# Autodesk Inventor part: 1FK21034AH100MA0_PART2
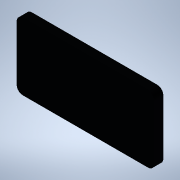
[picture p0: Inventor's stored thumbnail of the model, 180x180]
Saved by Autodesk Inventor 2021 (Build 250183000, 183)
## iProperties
Created: 2025-04
Part Number: 1FK21034AH100MA0_PART2
Material: Generic
Catalog Web Link: www.3dfindit.com
Description: -Servo synchronous motor
Document SubType Name: Modeling
Designer: psAdmin
Mass: 2.9597 g
Surface Area: 23.6483 cm^2
Volume: 2.9597 cm^3
Density: 1 g/cm^3
Appearance: PSOLRGB-38-46-56
Category: PARTsolutions
Title: 1FK21034AH100MA0_PART2
Author: Cadenas PARTsolutions
Comments: Servo synchronous motor
Sending System: PARTsolutions
Preprocessor: ST-DEVELOPER v19.3
PSOL_IDENT_0: {$CADENAS_DATA/23d-libs/siemens_ag/_cat_/39/97/1fk21034ah100ma0.prj},213 {VTYP=3D},{NB=1FK21034AH100
PSOL_IDENT_1: MA0_PART2},{LINA=1FK21034AH100MA0_PART2},{NN=1FK21034AH100MA0_PART2},{NOPRJ=TRUE},{DATE=19.08.2025 1
PSOL_IDENT_2: 4:00:33},{GEOMDATE=30.07.2025 02:02:21},{VERSION=},{LINEID=10},{WBVAR=},{WBNUMERIC=}  {NB=1FK21034AH
PSOL_IDENT_3: 100MA0_PART2},{LINA=1FK21034AH100MA0_PART2},{KT=DUMMY},{PREVIEW=../../../_pool_/d3/78/p_d211_xx_0093
PSOL_IDENT_4: 4j.png},{DESCSHORT=SIMOTICS S-1FK2 HD, SINAMICS S210 3AC 400V-480V, 1.01 Nm, 4500 rpm},{DESCLONG=SIM
PSOL_IDENT_5: OTICS S-1FK2 HD servo motor M0=1.27 Nm; PN = 0.48 kW at nN=4500 rpm (380-480 V); PN = 0.3 kW at nN=2
PSOL_IDENT_6: 500 rpm (200-240 V); with holding brake; degree of protection IP64; cylindrical shaft D14 x 30 mm; a
PSOL_IDENT_7: bsolute encoder 22-bit + 12-bit multiturn (encoder AM22DQC); with OCC interface; plug size M17, rota
PSOL_IDENT_8: table; SIMOTICS S-1FK2 servomotorfor a wide range of uses in industrial environments. SIMOTICS S‑1FK
PSOL_IDENT_9: 2 servomotors are compact synchronous motors with a high dynamic performance that set themselves apa
PSOL_IDENT_10: rt as a result of their high power density, degree of protection and overload capability. The motors
PSOL_IDENT_11: are available in two variants: as High Dynamic variant (highest dynamic performance as a result of
PSOL_IDENT_12: the low intrinsic moment of inertia for applications demanding a high dynamic performance with low m
PSOL_IDENT_13: oved masses) - and as Compact variant (precise and stable closed-loop control for medium up to large
PSOL_IDENT_14: moved masses as a result of a medium intrinsic moment of inertia). SIMOTICSS‑1FK2 servomotors fully
PSOL_IDENT_15: exploit their strengths in a system with the SINAMICSS210 frequency converter and simple connection
PSOL_IDENT_16: using the one cable connection (OCC). Advantages include the short control and positioning times, f
PSOL_IDENT_17: ast and precise correction of disturbing quantities as well as stable control with a high dynamic pe
PSOL_IDENT_18: rformance. The servo motors can be configured to address a wide range of requirements. For example w
PSOL_IDENT_19: ith and without holding brake, IP64 or IP65 degree of protection, singleturn or multiturn absolute e
PSOL_IDENT_20: ncoders - to name just a few. Further, the servomotors are available in different shaft heights exte
PSOL_IDENT_21: nding from 20 to 100. A shaft sealing ring is available to achieve an IP65 degree of protection and
PSOL_IDENT_22: for subsequent mounting at the motor or as spare part. SIMOTICS - the optimum motor for each and eve
PSOL_IDENT_23: ry motion control application.},{INTNO=195125454019},{SUPPLIERALTNO=1FK2103-4AH10-0MA0},{MANUID=1FK2
PSOL_IDENT_24: 1034AH100MA0},{MANUNAME=Siemens},{MANUTYPEDESC=SYNCHRONOUS MOTOR 1FK2 HD 1,27 NM},{AAU732=SIMOTICS},
PSOL_IDENT_25: {AAO057=S-1FK2},{AAU734=SIMOTICS S-1FK2 HD servo motor M0=1.27 Nm; PN = 0.48 kW at nN=4500 rpm (380-
PSOL_IDENT_26: 480 V); PN = 0.3 kW at nN=2500 rpm (200-240 V); with holding brake; degree of protection IP64; cylin
PSOL_IDENT_27: drical shaft D14 x 30 mm; absolute encoder 22-bit + 12-bit multiturn (encoder AM22DQC); with OCC int
PSOL_IDENT_28: erface; plug size M17, rotatable;},{AAW338=SYNCHRONOUS MOTOR 1FK2 HD 1,27 NM},{AAO742=SIMOTICS},{AAO
PSOL_IDENT_29: 663=4034106444921},{NOCUPEROU=1},{PRICEQUANTITY=1},{QUANTITYMIN=1},{QUANTITYINT=1},{CTN=85015100},{C
PSOL_IDENT_30: OO=RO},{AAO676=1FK2103-4AH10-0MA0},{AAO677=Siemens AG},{ORDERUNIT=C62},{CONTENTUNIT=C62}
NB: 1FK21034AH100MA0_PART2
NT: Servo synchronous motor
NBSYN: $MANUID._PART2
LINA: 1FK21034AH100MA0_PART2
CATALOG: SIEMENS
PREVIEW: ../../../_pool_/d3/78/p_d211_xx_00934j.png
DESCSHORT: SIMOTICS S-1FK2 HD, SINAMICS S210 3AC 400V-480V, 1.01 Nm, 4500 rpm
DESCLONG: SIMOTICS S-1FK2 HD servo motor M0=1.27 Nm; PN = 0.48 kW at nN=4500 rpm (380-480 V); PN = 0.3 kW at nN=2500 rpm (200-240 V); with holding brake; degree of protec
INTNO: 195125454019
SUPPLIERALTNO: 1FK2103-4AH10-0MA0
MANUID: 1FK21034AH100MA0
MANUNAME: Siemens
MANUTYPEDESC: SYNCHRONOUS MOTOR 1FK2 HD 1,27 NM
AAU732: SIMOTICS
AAO057: S-1FK2
AAU734: SIMOTICS S-1FK2 HD servo motor M0=1.27 Nm; PN = 0.48 kW at nN=4500 rpm (380-480 V); PN = 0.3 kW at nN=2500 rpm (200-240 V); with holding brake; degree of protec
AAW338: SYNCHRONOUS MOTOR 1FK2 HD 1,27 NM
AAO742: SIMOTICS
AAO663: 4034106444921.0
NOCUPEROU: 1
PRICEQUANTITY: 1
QUANTITYMIN: 1
QUANTITYINT: 1
CTN: 85015100
COO: RO
ARTICLENO: 1FK21034AH100MA0_PART2
BOMINFO: 1FK21034AH100MA0_PART2
CREATOR: CADENAS GmbH
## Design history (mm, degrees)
feature "2025_04_17_15_09_00_0236"
body "Solid1"
